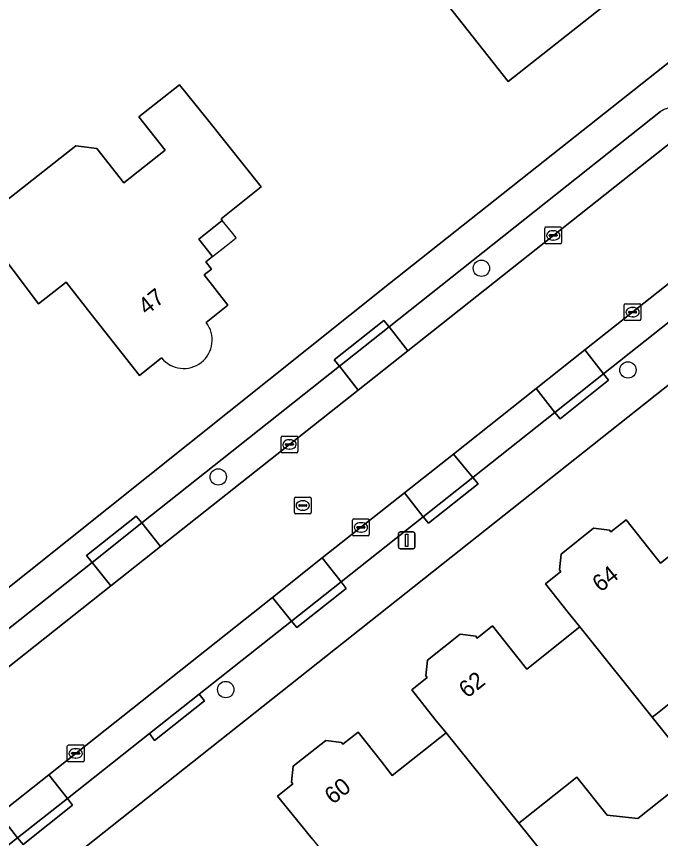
# Model space of a CAD drawing. Extents: x 159626 to 160723, y 388173 to 389416.
# Drawn here: x 160026.77 to 160065.22, y 388614.49 to 388663.53 of the extents above; entities that cross this region are included whole.
import ezdxf

# ---------------------------------------------------------------- set-up
doc = ezdxf.new("R2010")
doc.units = 0
for name, color, linetype in [('IMGEO_Boom', 7, 'Continuous'), ('IMGEO_Erf', 7, 'Continuous'), ('IMGEO_Kolk', 7, 'Continuous'), ('IMGEO_Lichtmast', 7, 'Continuous'), ('IMGEO_Muur', 7, 'Continuous'), ('IMGEO_Pand', 7, 'Continuous'), ('IMGEO_Pand_nummerreeks', 7, 'Continuous'), ('IMGEO_Pand_overbouw', 7, 'Continuous'), ('IMGEO_Parkeervlak_open', 7, 'Continuous'), ('IMGEO_Rijbaan_lokaal_gesloten', 7, 'Continuous'), ('IMGEO_Rioolput', 7, 'Continuous'), ('IMGEO_Voetpad_open', 7, 'Continuous')]:
    doc.layers.add(name, color=color, linetype=linetype)

msp = doc.modelspace()

# ---------------------------------------------------------------- linework, layer by layer
at = {"layer": 'IMGEO_Boom'}
for centre in [(160054.525, 388648.505), (160063.273, 388642.444), (160038.817, 388636.062), (160039.263, 388623.379)]:
    msp.add_circle(centre, 0.489, dxfattribs=at)
at = {"layer": 'IMGEO_Erf'}
msp.add_lwpolyline([(160056.693, 388678.249), (160063.169, 388670.081), (160063.615, 388670.429), (160064.434, 388669.453), (160063.937, 388669.097), (160065.532, 388667.078), (160056.128, 388659.649), (160047.981, 388669.96), (160042.833, 388665.893), (160042.005, 388666.942), (160047.104, 388670.998), (160047.319, 388670.784), (160047.436, 388670.871)], close=True, dxfattribs=at)
for points in [[(160005.787, 388613.115), (160049.042, 388647.598), (160059.258, 388655.688), (160070.681, 388664.734)], [(160030.307, 388655.804), (160031.57, 388655.651), (160033.175, 388653.603), (160035.636, 388655.54), (160034.071, 388657.528), (160036.509, 388659.448), (160038.257, 388657.27), (160041.386, 388653.37), (160038.983, 388651.446), (160039.052, 388651.36), (160037.662, 388650.239), (160038.468, 388649.206), (160038.066, 388648.889), (160038.404, 388648.457), (160037.965, 388648.112), (160039.388, 388646.307), (160038.099, 388645.273)], [(160035.421, 388643.16), (160034.11, 388642.119), (160031.017, 388646.047), (160029.737, 388647.674), (160028.086, 388646.375), (160024.983, 388650.487), (160025.136, 388651.75), (160030.307, 388655.804)], [(160080.808, 388653.527), (160013.38, 388600.15)], [(160087.833, 388634.71), (160085.998, 388634.913), (160084.195, 388637.184), (160080.904, 388634.573), (160080.632, 388634.358), (160083.244, 388631.068), (160079.881, 388628.4), (160078.045, 388628.603), (160076.242, 388630.874), (160072.951, 388628.263), (160072.696, 388628.061), (160075.332, 388624.79), (160071.859, 388622.035), (160070.022, 388622.238), (160068.219, 388624.509), (160064.928, 388621.898), (160064.719, 388621.733), (160067.349, 388618.457), (160063.859, 388615.688), (160062.023, 388615.891), (160060.22, 388618.162), (160056.929, 388615.551), (160056.754, 388615.412), (160059.391, 388612.143)], [(160044.419, 388614.476), (160043.741, 388615.309), (160042.358, 388617.027), (160043.275, 388617.754), (160043.195, 388617.856), (160043.29, 388618.8), (160045.233, 388620.341), (160046.174, 388620.219), (160046.254, 388620.117), (160047.17, 388620.843), (160048.538, 388619.101), (160049.202, 388618.256), (160052.412, 388620.794), (160051.745, 388621.621), (160050.376, 388623.362), (160051.293, 388624.089), (160051.213, 388624.191), (160051.308, 388625.135), (160053.251, 388626.676), (160054.192, 388626.554), (160054.272, 388626.452), (160055.188, 388627.178), (160056.548, 388625.465), (160057.232, 388624.604), (160060.402, 388627.11), (160059.708, 388627.975), (160058.347, 388629.687), (160059.264, 388630.414), (160059.184, 388630.516), (160059.279, 388631.46), (160061.222, 388633.001), (160062.163, 388632.879), (160062.243, 388632.777), (160063.159, 388633.503), (160064.528, 388631.783), (160065.218, 388630.916), (160068.38, 388633.416)]]:
    msp.add_lwpolyline(points, dxfattribs=at)
msp.add_arc((160036.746, 388644.234), 1.706, 219.0425, 37.5059, dxfattribs=at)
at = {"layer": 'IMGEO_Kolk'}
for p, q in [((160058.309, 388650.041), (160058.309, 388650.893)), ((160058.384, 388650.967), (160059.236, 388650.967)), ((160059.31, 388650.893), (160059.31, 388650.041)), ((160058.568, 388650.461), (160058.568, 388650.473)), ((160059.006, 388650.424), (160058.608, 388650.424)), ((160058.611, 388650.51), (160059.009, 388650.51)), ((160058.797, 388650.747), (160058.822, 388650.747)), ((160059.052, 388650.473), (160059.052, 388650.461)), ((160059.236, 388649.967), (160058.384, 388649.967)), ((160058.82, 388650.187), (160058.795, 388650.187)), ((160063.123, 388646.389), (160063.975, 388646.389)), ((160063.048, 388645.463), (160063.048, 388646.315)), ((160063.35, 388645.932), (160063.748, 388645.932)), ((160063.536, 388646.169), (160063.561, 388646.169)), ((160064.049, 388646.315), (160064.049, 388645.463)), ((160063.307, 388645.883), (160063.307, 388645.895)), ((160063.745, 388645.846), (160063.347, 388645.846)), ((160063.559, 388645.609), (160063.534, 388645.609)), ((160063.791, 388645.895), (160063.791, 388645.883)), ((160063.975, 388645.389), (160063.123, 388645.389)), ((160042.567, 388637.574), (160042.567, 388638.426)), ((160042.642, 388638.5), (160043.494, 388638.5)), ((160043.055, 388638.28), (160043.08, 388638.28)), ((160043.568, 388638.426), (160043.568, 388637.574)), ((160042.826, 388637.994), (160042.826, 388638.006)), ((160043.264, 388637.957), (160042.866, 388637.957)), ((160042.869, 388638.043), (160043.267, 388638.043)), ((160043.078, 388637.72), (160043.053, 388637.72)), ((160043.31, 388638.006), (160043.31, 388637.994)), ((160043.494, 388637.5), (160042.642, 388637.5)), ((160046.831, 388632.626), (160046.831, 388633.478)), ((160046.906, 388633.552), (160047.758, 388633.552)), ((160047.319, 388633.332), (160047.344, 388633.332)), ((160047.832, 388633.478), (160047.832, 388632.626)), ((160047.09, 388633.046), (160047.09, 388633.058)), ((160047.528, 388633.009), (160047.13, 388633.009)), ((160047.133, 388633.095), (160047.531, 388633.095)), ((160047.342, 388632.772), (160047.317, 388632.772)), ((160047.574, 388633.058), (160047.574, 388633.046)), ((160047.758, 388632.552), (160046.906, 388632.552)), ((160029.802, 388619.146), (160029.802, 388619.998)), ((160029.877, 388620.072), (160030.729, 388620.072)), ((160030.803, 388619.998), (160030.803, 388619.146)), ((160030.061, 388619.566), (160030.061, 388619.578)), ((160030.499, 388619.529), (160030.101, 388619.529)), ((160030.104, 388619.615), (160030.502, 388619.615)), ((160030.29, 388619.852), (160030.315, 388619.852)), ((160030.545, 388619.578), (160030.545, 388619.566)), ((160030.729, 388619.072), (160029.877, 388619.072)), ((160030.313, 388619.292), (160030.288, 388619.292))]:
    msp.add_line(p, q, dxfattribs=at)
for points in [[(160058.309, 388650.041), (160058.309, 388650.893)], [(160058.384, 388650.967), (160059.236, 388650.967)], [(160059.31, 388650.893), (160059.31, 388650.041)], [(160059.236, 388649.967), (160058.384, 388649.967)], [(160063.123, 388646.389), (160063.975, 388646.389)], [(160063.048, 388645.463), (160063.048, 388646.315)], [(160064.049, 388646.315), (160064.049, 388645.463)], [(160063.975, 388645.389), (160063.123, 388645.389)], [(160042.567, 388637.574), (160042.567, 388638.426)], [(160042.642, 388638.5), (160043.494, 388638.5)], [(160043.568, 388638.426), (160043.568, 388637.574)], [(160043.494, 388637.5), (160042.642, 388637.5)], [(160046.831, 388632.626), (160046.831, 388633.478)], [(160046.906, 388633.552), (160047.758, 388633.552)], [(160047.832, 388633.478), (160047.832, 388632.626)], [(160047.758, 388632.552), (160046.906, 388632.552)], [(160029.802, 388619.146), (160029.802, 388619.998)], [(160029.877, 388620.072), (160030.729, 388620.072)], [(160030.803, 388619.998), (160030.803, 388619.146)], [(160030.729, 388619.072), (160029.877, 388619.072)]]:
    msp.add_lwpolyline(points, dxfattribs=at)
for centre, radius, start, end in [((160058.386, 388650.891), 0.0765, 91.552, 178.448), ((160058.386, 388650.891), 0.0765, 91.552, 178.448), ((160059.234, 388650.891), 0.0765, 1.552, 88.448), ((160059.234, 388650.891), 0.0765, 1.552, 88.448), ((160058.608, 388650.47), 0.0403, 85.8775, 175.7526), ((160058.605, 388650.46), 0.0366, 178.938, 274.7102), ((160059.009, 388650.467), 0.043, 264.8664, 352.4533), ((160059.013, 388650.472), 0.0386, 1.7309, 96.639), ((160058.386, 388650.043), 0.0765, 181.552, 268.448), ((160058.386, 388650.043), 0.0765, 181.552, 268.448), ((160059.234, 388650.043), 0.0765, 271.552, 358.448), ((160059.234, 388650.043), 0.0765, 271.552, 358.448), ((160063.125, 388646.313), 0.0765, 91.552, 178.448), ((160063.125, 388646.313), 0.0765, 91.552, 178.448), ((160063.973, 388646.313), 0.0765, 1.552, 88.448), ((160063.973, 388646.313), 0.0765, 1.552, 88.448), ((160063.347, 388645.892), 0.0403, 85.8775, 175.7526), ((160063.752, 388645.894), 0.0386, 1.7309, 96.639), ((160063.125, 388645.465), 0.0765, 181.552, 268.448), ((160063.125, 388645.465), 0.0765, 181.552, 268.448), ((160063.344, 388645.882), 0.0366, 178.938, 274.7102), ((160063.748, 388645.889), 0.043, 264.8664, 352.4533), ((160063.973, 388645.465), 0.0765, 271.552, 358.448), ((160063.973, 388645.465), 0.0765, 271.552, 358.448), ((160042.644, 388638.424), 0.0765, 91.552, 178.448), ((160042.644, 388638.424), 0.0765, 91.552, 178.448), ((160043.492, 388638.424), 0.0765, 1.552, 88.448), ((160043.492, 388638.424), 0.0765, 1.552, 88.448), ((160042.644, 388637.576), 0.0765, 181.552, 268.448), ((160042.644, 388637.576), 0.0765, 181.552, 268.448), ((160042.866, 388638.003), 0.0403, 85.8775, 175.7526), ((160042.863, 388637.993), 0.0366, 178.938, 274.7102), ((160043.267, 388638), 0.043, 264.8664, 352.4533), ((160043.271, 388638.005), 0.0386, 1.7309, 96.639), ((160043.492, 388637.576), 0.0765, 271.552, 358.448), ((160043.492, 388637.576), 0.0765, 271.552, 358.448), ((160046.908, 388633.476), 0.0765, 91.552, 178.448), ((160046.908, 388633.476), 0.0765, 91.552, 178.448), ((160047.756, 388633.476), 0.0765, 1.552, 88.448), ((160047.756, 388633.476), 0.0765, 1.552, 88.448), ((160047.13, 388633.055), 0.0403, 85.8775, 175.7526), ((160047.127, 388633.045), 0.0366, 178.938, 274.7102), ((160047.531, 388633.052), 0.043, 264.8664, 352.4533), ((160047.535, 388633.057), 0.0386, 1.7309, 96.639), ((160046.908, 388632.628), 0.0765, 181.552, 268.448), ((160046.908, 388632.628), 0.0765, 181.552, 268.448), ((160047.756, 388632.628), 0.0765, 271.552, 358.448), ((160047.756, 388632.628), 0.0765, 271.552, 358.448), ((160029.879, 388619.996), 0.0765, 91.552, 178.448), ((160029.879, 388619.996), 0.0765, 91.552, 178.448), ((160030.727, 388619.996), 0.0765, 1.552, 88.448), ((160030.727, 388619.996), 0.0765, 1.552, 88.448), ((160030.101, 388619.575), 0.0403, 85.8775, 175.7526), ((160030.098, 388619.565), 0.0366, 178.938, 274.7102), ((160030.502, 388619.572), 0.043, 264.8664, 352.4533), ((160030.506, 388619.577), 0.0386, 1.7309, 96.639), ((160029.879, 388619.148), 0.0765, 181.552, 268.448), ((160029.879, 388619.148), 0.0765, 181.552, 268.448), ((160030.727, 388619.148), 0.0765, 271.552, 358.448), ((160030.727, 388619.148), 0.0765, 271.552, 358.448)]:
    msp.add_arc(centre, radius, start, end, dxfattribs=at)
for centre, major_axis, ratio, start_param, end_param in [((160058.796, 388650.467), (-0.387, 0.002), 0.722429, 4.712389, 7.853982), ((160058.821, 388650.467), (-0.39, 0.002), 0.717154, 1.570796, 4.712389), ((160063.535, 388645.889), (-0.387, 0.002), 0.722429, 4.712389, 7.853982), ((160063.56, 388645.889), (-0.39, 0.002), 0.717154, 1.570796, 4.712389), ((160043.054, 388638), (-0.387, 0.002), 0.722429, 4.712389, 7.853982), ((160043.079, 388638), (-0.39, 0.002), 0.717154, 1.570796, 4.712389), ((160047.318, 388633.052), (-0.387, 0.002), 0.722429, 4.712389, 7.853982), ((160047.343, 388633.052), (-0.39, 0.002), 0.717154, 1.570796, 4.712389), ((160030.289, 388619.572), (-0.387, 0.002), 0.722429, 4.712389, 7.853982), ((160030.314, 388619.572), (-0.39, 0.002), 0.717154, 1.570796, 4.712389)]:
    msp.add_ellipse(centre, major_axis=major_axis, ratio=ratio, start_param=start_param, end_param=end_param, dxfattribs=at)
at = {"layer": 'IMGEO_Lichtmast'}
for p, q in [((160049.566, 388631.879), (160049.566, 388632.679)), ((160049.566, 388632.679), (160049.566, 388631.879)), ((160049.666, 388632.779), (160050.456, 388632.779)), ((160050.456, 388632.779), (160049.666, 388632.779)), ((160050.556, 388632.679), (160050.556, 388631.879)), ((160050.556, 388631.879), (160050.556, 388632.679)), ((160050.456, 388631.779), (160049.666, 388631.779)), ((160049.666, 388631.779), (160050.456, 388631.779))]:
    msp.add_line(p, q, dxfattribs=at)
msp.add_lwpolyline([(160049.986, 388632.654), (160050.136, 388632.654), (160050.136, 388631.904), (160049.986, 388631.904), (160049.986, 388632.654)], dxfattribs=at)
for centre, start, end in [((160049.666, 388632.679), 90, 180), ((160049.666, 388632.679), 90, 180), ((160050.456, 388632.679), 0, 90), ((160050.456, 388632.679), 360, 90), ((160049.666, 388631.879), 180, 270), ((160049.666, 388631.879), 180, 270), ((160050.456, 388631.879), 270, 0), ((160050.456, 388631.879), 270, 0)]:
    msp.add_arc(centre, 0.1, start, end, dxfattribs=at)
at = {"layer": 'IMGEO_Muur'}
msp.add_lwpolyline([(160059.258, 388655.688), (160049.042, 388647.598)], dxfattribs=at)
at = {"layer": 'IMGEO_Pand'}
for points in [[(160056.128, 388659.649), (160065.532, 388667.078), (160063.937, 388669.097), (160064.434, 388669.453), (160063.615, 388670.429), (160063.169, 388670.081), (160056.693, 388678.249), (160047.436, 388670.871), (160047.319, 388670.784), (160047.104, 388670.998), (160042.005, 388666.942), (160042.833, 388665.893), (160047.981, 388669.96)], [(160072.696, 388628.061), (160068.38, 388633.416), (160065.218, 388630.916), (160064.528, 388631.783), (160063.159, 388633.503), (160062.243, 388632.777), (160062.163, 388632.879), (160061.222, 388633.001), (160059.279, 388631.46), (160059.184, 388630.516), (160059.264, 388630.414), (160058.347, 388629.687), (160059.708, 388627.975), (160060.402, 388627.11), (160064.719, 388621.733), (160064.928, 388621.898), (160068.219, 388624.509), (160070.022, 388622.238), (160071.859, 388622.035), (160075.332, 388624.79)], [(160064.719, 388621.733), (160060.402, 388627.11), (160057.232, 388624.604), (160056.548, 388625.465), (160055.188, 388627.178), (160054.272, 388626.452), (160054.192, 388626.554), (160053.251, 388626.676), (160051.308, 388625.135), (160051.213, 388624.191), (160051.293, 388624.089), (160050.376, 388623.362), (160051.745, 388621.621), (160052.412, 388620.794), (160056.754, 388615.412), (160056.929, 388615.551), (160060.22, 388618.162), (160062.023, 388615.891), (160063.859, 388615.688), (160067.349, 388618.457)], [(160056.754, 388615.412), (160052.412, 388620.794), (160049.202, 388618.256), (160048.538, 388619.101), (160047.17, 388620.843), (160046.254, 388620.117), (160046.174, 388620.219), (160045.233, 388620.341), (160043.29, 388618.8), (160043.195, 388617.856), (160043.275, 388617.754), (160042.358, 388617.027), (160043.741, 388615.309), (160044.419, 388614.476), (160048.796, 388609.098), (160048.945, 388609.216), (160052.236, 388611.827), (160054.039, 388609.556), (160055.875, 388609.353), (160059.391, 388612.143)]]:
    msp.add_lwpolyline(points, close=True, dxfattribs=at)
msp.add_lwpolyline([(160038.099, 388645.273), (160039.388, 388646.307), (160037.965, 388648.112), (160038.404, 388648.457), (160038.066, 388648.889), (160038.468, 388649.206), (160037.662, 388650.239), (160039.052, 388651.36), (160038.983, 388651.446), (160041.386, 388653.37), (160038.257, 388657.27), (160036.509, 388659.448), (160034.071, 388657.528), (160035.636, 388655.54), (160033.175, 388653.603), (160031.57, 388655.651), (160030.307, 388655.804), (160025.136, 388651.75), (160024.983, 388650.487), (160028.086, 388646.375), (160029.737, 388647.674), (160031.017, 388646.047), (160034.11, 388642.119), (160035.421, 388643.16)], dxfattribs=at)
msp.add_arc((160036.746, 388644.234), 1.706, 219.0425, 37.5059, dxfattribs=at)
at = {"layer": 'IMGEO_Pand_overbouw'}
msp.add_lwpolyline([(160039.052, 388651.36), (160037.662, 388650.239), (160038.468, 388649.206), (160039.282, 388649.849), (160039.878, 388650.319), (160039.679, 388650.57)], close=True, dxfattribs=at)
at = {"layer": 'IMGEO_Parkeervlak_open'}
for points in [[(160065.22, 388657.847), (160049.009, 388645.004), (160050.132, 388643.587), (160068.619, 388658.215)], [(160073.352, 388653.65), (160060.695, 388643.631), (160061.819, 388642.213), (160066.782, 388646.145), (160069.741, 388648.491)]]:
    msp.add_lwpolyline(points, dxfattribs=at)
for points in [[(160050.132, 388643.587), (160049.009, 388645.004), (160046.049, 388642.659), (160047.169, 388641.243)], [(160061.819, 388642.213), (160060.695, 388643.631), (160057.792, 388641.333), (160058.917, 388639.912)], [(160047.169, 388641.243), (160046.049, 388642.659), (160034.252, 388633.313), (160035.367, 388631.905)], [(160058.917, 388639.912), (160057.792, 388641.333), (160052.856, 388637.426), (160054.016, 388636.027)], [(160054.016, 388636.027), (160052.856, 388637.426), (160049.93, 388635.11), (160051.055, 388633.688)], [(160051.055, 388633.688), (160049.93, 388635.11), (160045.026, 388631.228), (160046.143, 388629.798)], [(160035.367, 388631.905), (160034.252, 388633.313), (160031.285, 388630.963), (160032.398, 388629.556)], [(160046.143, 388629.798), (160045.026, 388631.228), (160042.056, 388628.877), (160043.182, 388627.455)], [(160032.398, 388629.556), (160031.285, 388630.963), (160019.477, 388621.608), (160020.566, 388620.194)], [(160037.684, 388623.105), (160043.182, 388627.455), (160042.056, 388628.877), (160028.691, 388618.298), (160029.813, 388616.878), (160034.702, 388620.751)], [(160029.813, 388616.878), (160028.691, 388618.298), (160025.716, 388615.943), (160026.836, 388614.526)], [(160026.836, 388614.526), (160025.716, 388615.943), (160020.619, 388611.908), (160021.756, 388610.506)]]:
    msp.add_lwpolyline(points, close=True, dxfattribs=at)
msp.add_arc((160065.833, 388657.074), 0.987, 82.9057, 128.4077, dxfattribs=at)
at = {"layer": 'IMGEO_Rijbaan_lokaal_gesloten'}
for points in [[(160167.383, 388736.528), (160164.446, 388734.198), (160154.322, 388726.169), (160153.45, 388725.499), (160143.876, 388717.854), (160143.646, 388717.671), (160143.177, 388717.325), (160085.885, 388671.953), (160085.177, 388671.383), (160084.775, 388671.059), (160074.107, 388662.597), (160068.619, 388658.215), (160050.132, 388643.587), (160047.169, 388641.243), (160035.367, 388631.905), (160032.398, 388629.556), (160020.566, 388620.194), (160017.62, 388617.863), (160009.366, 388611.332), (160008.998, 388611.041), (160000, 388603.924), (159995.738, 388600.553), (159983.064, 388590.517)], [(160025.716, 388615.943), (160028.691, 388618.298), (160042.056, 388628.877), (160045.026, 388631.228), (160049.93, 388635.11), (160052.856, 388637.426), (160057.792, 388641.333), (160060.695, 388643.631), (160073.352, 388653.65), (160073.624, 388653.858), (160076.667, 388656.181), (160076.921, 388656.375), (160090.898, 388667.506)]]:
    msp.add_lwpolyline(points, dxfattribs=at)
at = {"layer": 'IMGEO_Rioolput'}
for p, q in [((160043.361, 388633.93), (160043.361, 388634.782)), ((160043.436, 388634.856), (160044.288, 388634.856)), ((160043.849, 388634.636), (160043.874, 388634.636)), ((160044.362, 388634.782), (160044.362, 388633.93)), ((160043.62, 388634.35), (160043.62, 388634.362)), ((160044.058, 388634.313), (160043.66, 388634.313)), ((160043.663, 388634.399), (160044.061, 388634.399)), ((160044.104, 388634.362), (160044.104, 388634.35)), ((160044.288, 388633.856), (160043.436, 388633.856)), ((160043.872, 388634.076), (160043.847, 388634.076))]:
    msp.add_line(p, q, dxfattribs=at)
for points in [[(160043.361, 388633.93), (160043.361, 388634.782)], [(160043.436, 388634.856), (160044.288, 388634.856)], [(160044.362, 388634.782), (160044.362, 388633.93)], [(160044.288, 388633.856), (160043.436, 388633.856)]]:
    msp.add_lwpolyline(points, dxfattribs=at)
for centre, radius, start, end in [((160043.438, 388634.78), 0.0765, 91.552, 178.448), ((160043.438, 388634.78), 0.0765, 91.552, 178.448), ((160044.286, 388634.78), 0.0765, 1.552, 88.448), ((160044.286, 388634.78), 0.0765, 1.552, 88.448), ((160043.66, 388634.359), 0.0403, 85.8775, 175.7526), ((160043.657, 388634.349), 0.0366, 178.938, 274.7102), ((160044.061, 388634.356), 0.043, 264.8664, 352.4533), ((160044.065, 388634.361), 0.0386, 1.7309, 96.639), ((160043.438, 388633.932), 0.0765, 181.552, 268.448), ((160043.438, 388633.932), 0.0765, 181.552, 268.448), ((160044.286, 388633.932), 0.0765, 271.552, 358.448), ((160044.286, 388633.932), 0.0765, 271.552, 358.448)]:
    msp.add_arc(centre, radius, start, end, dxfattribs=at)
for centre, major_axis, ratio, start_param, end_param in [((160043.848, 388634.356), (-0.387, 0.002), 0.722429, 4.712389, 7.853982), ((160043.873, 388634.356), (-0.39, 0.002), 0.717154, 1.570796, 4.712389)]:
    msp.add_ellipse(centre, major_axis=major_axis, ratio=ratio, start_param=start_param, end_param=end_param, dxfattribs=at)
at = {"layer": 'IMGEO_Voetpad_open'}
for points in [[(160077.86, 388672.72), (160077.775, 388670.246), (160073.852, 388667.146), (160070.681, 388664.734), (160059.258, 388655.688), (160049.042, 388647.598), (160005.787, 388613.115)], [(160010.506, 388614.501), (160016.514, 388619.26), (160016.202, 388619.665), (160019.172, 388622.004), (160019.477, 388621.608), (160031.285, 388630.963), (160030.95, 388631.382), (160033.911, 388633.722), (160034.252, 388633.313), (160046.049, 388642.659), (160045.739, 388643.051), (160048.699, 388645.395), (160049.009, 388645.004), (160065.22, 388657.847)], [(159989.706, 388581.373), (160000, 388589.546), (160010.998, 388598.278), (160013.38, 388600.15), (160080.808, 388653.527), (160084.118, 388656.51)], [(160066.782, 388646.145), (160061.819, 388642.213), (160062.117, 388641.838), (160059.225, 388639.52), (160058.917, 388639.912), (160054.016, 388636.027), (160054.331, 388635.647), (160051.371, 388633.299), (160051.055, 388633.688), (160046.143, 388629.798), (160046.449, 388629.405), (160043.51, 388627.075), (160043.182, 388627.455), (160037.684, 388623.105), (160037.986, 388622.7), (160035.008, 388620.344), (160034.702, 388620.751), (160029.813, 388616.878), (160030.12, 388616.475), (160027.166, 388614.131), (160026.836, 388614.526), (160021.756, 388610.506)]]:
    msp.add_lwpolyline(points, dxfattribs=at)
for points in [[(160049.009, 388645.004), (160048.699, 388645.395), (160045.739, 388643.051), (160046.049, 388642.659)], [(160062.117, 388641.838), (160061.819, 388642.213), (160058.917, 388639.912), (160059.225, 388639.52)], [(160054.016, 388636.027), (160051.055, 388633.688), (160051.371, 388633.299), (160054.331, 388635.647)], [(160031.285, 388630.963), (160034.252, 388633.313), (160033.911, 388633.722), (160030.95, 388631.382)], [(160043.182, 388627.455), (160043.51, 388627.075), (160046.449, 388629.405), (160046.143, 388629.798)], [(160037.684, 388623.105), (160034.702, 388620.751), (160035.008, 388620.344), (160037.986, 388622.7)], [(160026.836, 388614.526), (160027.166, 388614.131), (160030.12, 388616.475), (160029.813, 388616.878)]]:
    msp.add_lwpolyline(points, close=True, dxfattribs=at)
msp.add_arc((160065.833, 388657.074), 0.987, 82.9057, 128.4077, dxfattribs=at)

# ---------------------------------------------------------------- texts
at = {"layer": 'IMGEO_Pand_nummerreeks'}
for s, rotation, p in [('47', 38.4314, (160034.535, 388645.674)), ('64', 38.4168, (160061.639, 388629.145)), ('62', 38.4168, (160053.673, 388622.824)), ('60', 38.4168, (160045.655, 388616.489))]:
    msp.add_text(s, height=1, rotation=rotation, dxfattribs=at).set_placement(p)

doc.saveas('drawing.dxf')
